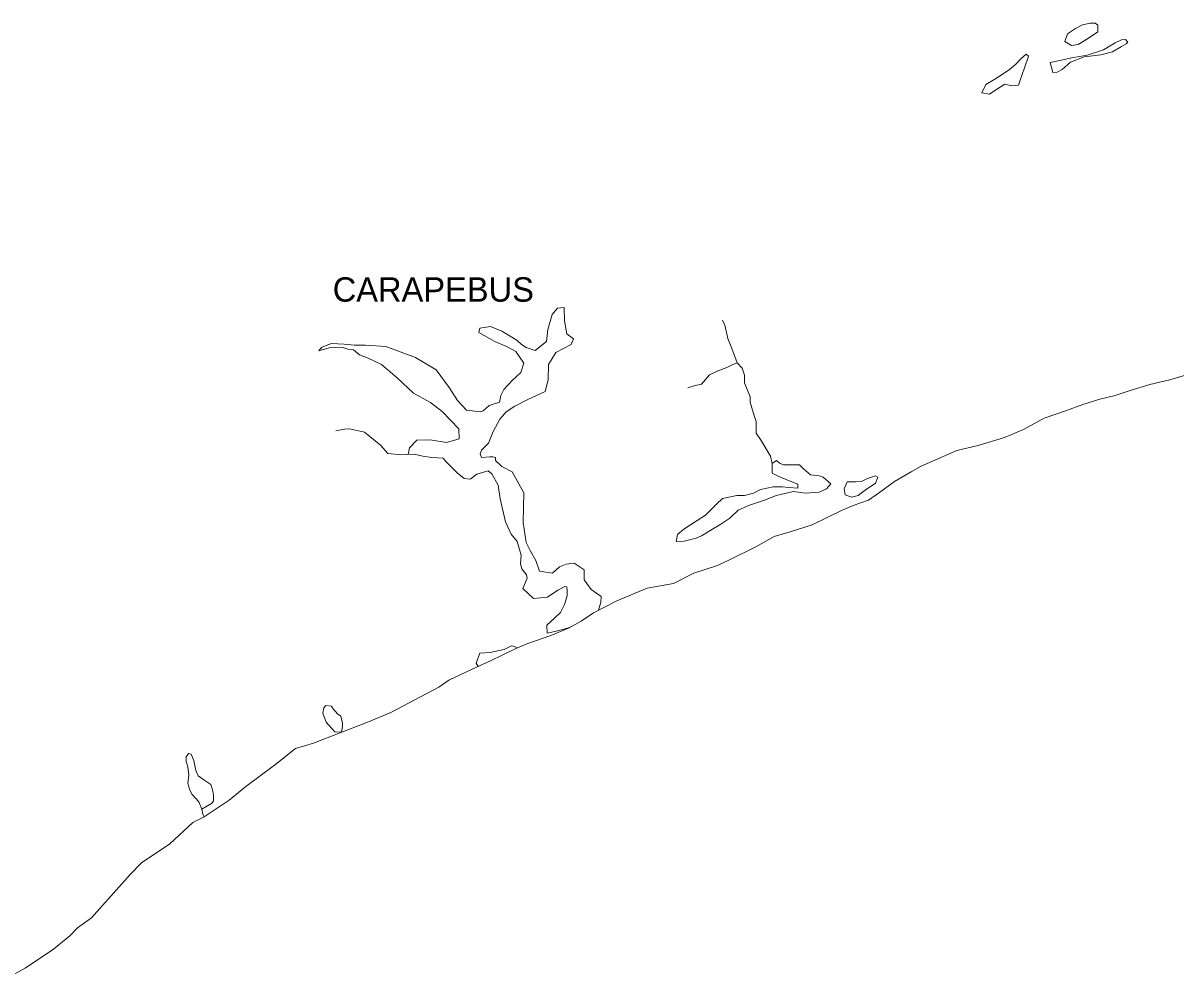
# Model space of a CAD drawing. Extents: x 47169 to 972804, y 7447977 to 9608469.
# Drawn here: x 218240 to 248175, y 7526939 to 7551895 of the extents above; entities that cross this region are included whole.
import ezdxf

# ---------------------------------------------------------------- set-up
doc = ezdxf.new("R2010")
doc.units = 0
doc.header["$LTSCALE"] = 270
doc.layers.add('1', color=7, linetype='Continuous', lineweight=13)
doc.layers.add('3', color=7, linetype='Continuous')

msp = doc.modelspace()

# ---------------------------------------------------------------- linework, layer by layer
at = {"layer": '1'}
for points in [[(246142.4, 7551840.9), (246145.3, 7551663.7), (245900.1, 7551504.6), (245634.5, 7551334.1), (245459.4, 7551309.1), (245292.4, 7551417.2), (245361.5, 7551617.8), (245565.7, 7551754), (245750, 7551845.7), (245945.4, 7551893.1), (246079.6, 7551895.3)], [(246760.5, 7551285.9), (246525.2, 7551149.1), (246227.2, 7551066.8), (245794.5, 7551015.4), (245435.4, 7550876.7), (245221.8, 7550684.8), (245088.7, 7550616.2), (244975.2, 7550614.4), (244909.1, 7550868.1), (245114.8, 7550915.8), (245474.9, 7550988.1), (245866, 7551060.9), (246297.3, 7551200.8), (246593.7, 7551382.9), (246757.6, 7551463.1), (246860.8, 7551464.8), (246923.8, 7551399.3), (246883.2, 7551354.3)], [(244143.6, 7550966.4), (244286.1, 7551090.6), (244348.9, 7551036.2), (244240.3, 7550735.3), (244122, 7550389.9), (244082.6, 7550278.5), (243917.6, 7550264.7), (243731.1, 7550306), (243424.6, 7550112.6), (243332.8, 7550044.7), (243136, 7550085.8), (243235.8, 7550297.9), (243471, 7550434.7), (243665.1, 7550559.8), (243848.8, 7550684.6), (244011.8, 7550820.2)], [(239214.6, 7539929.4), (239103.3, 7539794.6), (238908.7, 7539713.8), (238548.1, 7539685.6), (238248.3, 7539724.9), (237796, 7539628.7), (237693.6, 7539582.6), (237488.6, 7539501.6), (237098.8, 7539373.2), (236812.1, 7539246.5), (236588.7, 7539032.2), (236354, 7538884.2), (236057.9, 7538701.9), (235853.7, 7538576.5), (235720.6, 7538518.9), (235402.2, 7538435.9), (235196, 7538432.4), (235234.2, 7538610.3), (235397, 7538746.1), (235743.8, 7538973.5), (235958.1, 7539110.1), (236242, 7539403), (236404.6, 7539549.8), (236774.8, 7539622.5), (236970.7, 7539625.9), (237207, 7539685.2), (237391.1, 7539777), (237720.1, 7539849), (237957.3, 7539853), (238122.6, 7539833.6), (238360.2, 7539815.4), (238358.6, 7539915.1), (238161.1, 7540000.4), (237849.5, 7540128.2), (237693.5, 7540203.1), (237692, 7540291.7), (237689.2, 7540457.9), (237801.3, 7540537.3), (237885.1, 7540461.2), (237989, 7540418.6), (238133.4, 7540421), (238401.6, 7540425.5), (238506.6, 7540316.5), (238684.5, 7540164.3), (238912, 7540134.9), (239015.6, 7540103.4)], [(239583.5, 7539645.3), (239560.2, 7539800), (239639.8, 7539978.6), (239753.2, 7539980.5), (239856.4, 7539982.3), (240011.1, 7539984.8), (240164.5, 7540064.9), (240369.6, 7540134.8), (240432.1, 7540102.6), (240372.8, 7539946.5), (240107.6, 7539764.8), (240046.4, 7539719.5), (239924.2, 7539628.8), (239749.6, 7539581.6)], [(226507.1, 7533482.1), (226331.6, 7533490.1), (226110.6, 7533741.1), (226024.1, 7533972.2), (226052.7, 7534105.7), (226103.1, 7534173.1), (226247.8, 7534153.5), (226290.2, 7534087.7), (226405.9, 7533956.8), (226489.6, 7533891.8), (226534, 7533715.3), (226535.5, 7533626.6)]]:
    msp.add_lwpolyline(points, close=True, dxfattribs=at)
for points in [[(228237.7, 7540692.9), (228276.1, 7540859.7), (228468.6, 7541062.5), (228809, 7541068.5), (229233.2, 7540998.3), (229561.8, 7541092.6), (229557.2, 7541358.5), (229126.4, 7541805.3), (228823, 7542043.8), (228375.2, 7542279.8), (227955.5, 7542682.5), (227547, 7543030), (227203.6, 7543190.2), (226975.1, 7543274.9), (226818.1, 7543405.1), (226673.2, 7543424.7), (226517.5, 7543477.4), (226187.6, 7543460.5), (225920.7, 7543378.3), (226001.5, 7543479.4), (226247.5, 7543572.4), (226578.1, 7543556), (226846.9, 7543527.5), (227135.7, 7543532.5), (227662.6, 7543497.4), (228431.2, 7543211.6), (228963.1, 7542888.4), (229301.3, 7542428.9), (229523.9, 7542089.2), (229755.2, 7541838.4), (230117, 7541800.3), (230188.9, 7541823.7), (230341.3, 7541959.3), (230608, 7542052.5), (230646.4, 7542219.4), (230726.2, 7542375.9), (230938.8, 7542612.3), (231162.3, 7542815.6), (231240.7, 7543060.7), (231039.3, 7543367.5), (230789.5, 7543496.2), (230488, 7543623.9), (230071.1, 7543860.5), (230100.2, 7543971.8), (230378.1, 7544009.9), (230669.1, 7543893), (231065.3, 7543656), (231180.7, 7543547.2), (231305.8, 7543471.8), (231534.3, 7543387.1), (231829.5, 7543624.8), (231865.4, 7543935.7), (231982.6, 7544325.5), (232113.9, 7544494), (232289, 7544508.1), (232294.9, 7544164.7), (232362.7, 7543822.3), (232530, 7543692.2), (232470.6, 7543547.2), (232071.7, 7543340.9), (231881, 7543027.4), (231877.5, 7542628.4), (231800.1, 7542327.9), (231329.3, 7542109.3), (231012.2, 7541948.7), (230787.7, 7541800.8), (230676.3, 7541677), (230615.6, 7541609.5), (230445.8, 7541285.2), (230327.2, 7540984), (230144.6, 7540803.5), (230105, 7540703.1), (230147.8, 7540615.2), (230364.2, 7540630), (230436.5, 7540631.2), (230509, 7540610.4), (230510.4, 7540532.8), (230667.8, 7540380.4), (230938.4, 7540241), (231247.1, 7539692.3), (231233.1, 7539304.2), (231229.3, 7538927.4), (231300.1, 7538407.9), (231406.9, 7538199.2), (231555.8, 7537935.8), (231653.4, 7537660.5), (231984.4, 7537610.8), (232167.3, 7537769), (232341.5, 7537838.5), (232547.4, 7537864.2), (232808.2, 7537691.4), (232812.6, 7537436.6), (232992.2, 7537184.8), (233253.3, 7537000.9), (233245.6, 7536845.7), (233186.6, 7536678.5), (233187.1, 7536645.2)], [(237689.2, 7540457.9), (237647.9, 7540643.3), (237403.8, 7541049.2), (237276.7, 7541246.5), (237271.6, 7541545.6), (237206.2, 7541755), (237118.6, 7542052.7), (237116.4, 7542185.6), (236976.2, 7542548.9), (236972.8, 7542748.3), (236907.8, 7542935.5), (236781.7, 7543066.4), (236641.3, 7543440.7), (236543.9, 7543705), (236465.9, 7544047.2), (236401.8, 7544179.1)], [(217539.9, 7526938.7), (218295.3, 7527351.4), (219028.7, 7527841.2), (219455.4, 7528192.4), (219658, 7528395.6), (220014.1, 7528656.9), (221024.9, 7529783.2), (221318.5, 7530087.7), (222052.1, 7530577.4), (222650.6, 7531131), (222947, 7531280.4), (223589, 7531712.9), (224026.2, 7532064.2), (224799.6, 7532643), (225318.4, 7533051.2), (225780, 7533192.3), (226445.8, 7533447.8), (227162.9, 7533726.3), (227787.3, 7533992.1), (229034.2, 7534645.5), (229299.1, 7534827.4), (229902.7, 7535114.9), (230373.3, 7535333.6), (231017.7, 7535643.9), (231325, 7535771.1), (231940, 7535992.2), (232401, 7536177.4), (232727.9, 7536360.3), (233054.2, 7536576.5), (233657.5, 7536886), (234446, 7537220.7), (235124.7, 7537343.1), (235656.6, 7537607), (236272.1, 7537805.8), (236599.5, 7537966.4), (237264.6, 7538287.9), (237744.8, 7538561.9), (238155.4, 7538679.6), (238730, 7538866.5), (239487.2, 7539233.7), (239794.5, 7539360.8), (240194.5, 7539500.4), (240480, 7539704.6), (240867.3, 7539988), (241296.4, 7540238.9), (241562.1, 7540387.3), (242484, 7540790.3), (243038.9, 7540921.4), (243726.6, 7541132.1), (244218.4, 7541339.6), (244750, 7541636.4), (245334.9, 7541834.3), (245755.4, 7541985.1), (246196.8, 7542125.3), (246597.6, 7542220.4), (246987.5, 7542348.6), (247500.8, 7542512), (248014.7, 7542631.1), (249031.2, 7542935.5)], [(236781.7, 7543066.4), (236638.2, 7543008.5), (236515.4, 7542951.1), (236259, 7542858.1), (236064.7, 7542755.1), (235852, 7542518.8), (235687.5, 7542482.8), (235502.8, 7542424.3)], [(232462.3, 7536211.7), (232380.3, 7536177.1), (232051.7, 7536093.9), (231846.2, 7536046), (231842.6, 7536256.5), (232045.6, 7536448.3), (232198, 7536583.9), (232297.5, 7536796.2), (232365.9, 7537019), (232363.8, 7537140.8), (232361.9, 7537251.6), (232310.1, 7537261.8), (232126, 7537170), (231861, 7536988.1), (231490.3, 7536948.5), (231217.6, 7537209.7), (231326.5, 7537477.5), (231314.6, 7537566), (231188.2, 7537718.9), (231155, 7537851.3), (231171.8, 7538073.2), (231072.9, 7538426.1), (230914.7, 7538622.8), (230764.8, 7538941.6), (230630.7, 7539537.6), (230573, 7539891.2), (230413.1, 7540187.6), (230319, 7540263.6), (230021.2, 7540180.8), (229878.7, 7540067.6), (229848.2, 7540044.9), (229693.1, 7540064.4), (229515.1, 7540216.4), (229347.1, 7540379.7), (229221.1, 7540510.5), (229147.3, 7540597.9), (228858.1, 7540615), (228620.3, 7540644.1), (228392.5, 7540695.5), (228186.2, 7540692), (228062.6, 7540678.7), (227711.1, 7540716.9), (227521.6, 7540935.2), (227103, 7541271.4), (226719.8, 7541353.4), (226585.7, 7541351), (226359.5, 7541302.7)], [(230056.2, 7535184), (230003.1, 7535271.8), (230101.8, 7535528.3), (230369.7, 7535544), (230729.2, 7535627.8), (230923.6, 7535719.8), (230996.1, 7535698.9), (231048.1, 7535677.7), (231058.8, 7535655.7)], [(222947, 7531280.4), (222904.6, 7531346.1), (222881.6, 7531478.7), (222806.1, 7531665.7), (222627.3, 7531862), (222573.8, 7531971.9), (222519, 7532148.2), (222546.2, 7532359.2), (222521.6, 7532580.4), (222478, 7532712.6), (222475.6, 7532845.5), (222546.4, 7532924.4), (222608.7, 7532903.3), (222673.5, 7532738.3), (222729.6, 7532484.4), (222783.7, 7532341.3), (222961.1, 7532222.6), (223117.8, 7532114.5), (223161.4, 7531982.3), (223184.6, 7531838.7), (223187.3, 7531683.6), (223136.8, 7531627.3), (222881.6, 7531478.7)]]:
    msp.add_lwpolyline(points, dxfattribs=at)

# ---------------------------------------------------------------- texts
at = {"layer": '3'}
msp.add_text('CARAPEBUS', height=633.4, dxfattribs=at).set_placement((226280.1, 7544658.9))

doc.saveas('drawing.dxf')
